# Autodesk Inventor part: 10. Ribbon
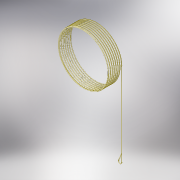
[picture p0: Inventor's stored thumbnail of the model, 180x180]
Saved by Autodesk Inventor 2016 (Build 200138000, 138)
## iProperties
Created: 2016-01
Part Number: 10. Ribbon
Material: Generic
Document SubType Name: Modeling
Designer: Black Falcon
Density: 1 g/cm^3
Appearance: Nylon 6
Author: Black Falcon
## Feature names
1. Coil1
2. Revolution1
3. Extrusion1
4. Sweep1
5. Extrusion2
## Parameters: d0 = 1.27 mm, d1 = 38.1 mm, d2 = 25.4 mm, d3 = 20.32 mm, d5 = 0, d6 = 90 deg, d7 = 90 deg, d8 = 0, d9 = 0, d10 = 90 deg, d11 = 127 mm, d12 = 0, d13 = 0, d14 = 0, d15 = 0, d16 = 381 mm, d17 = 0
